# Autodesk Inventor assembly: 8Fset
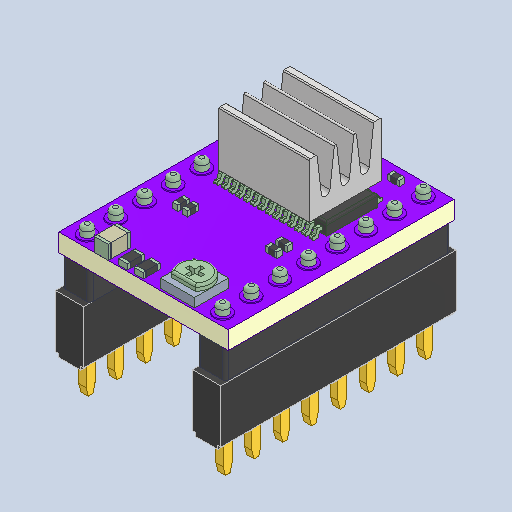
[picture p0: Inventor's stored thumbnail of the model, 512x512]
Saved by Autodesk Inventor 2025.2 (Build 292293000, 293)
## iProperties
Created: 2025-04
Part Number: 8Fset
Description: PART--DESC
Document SubType Name: Assembly
Designer: BennF
Author: BennF
Revision Number: NONE
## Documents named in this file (4)
- C:\Users\BennF\Nextcloud\Benutzer\CNC JarBeRi\existing parts\Electronics\RepRap A4988 Shied (USE WITHOUT ARDUINO)\reprap-a4988-1.snapshot.1\RepRap\RepRap\8Fset.iam
- C:\Users\BennF\Nextcloud\Benutzer\CNC JarBeRi\existing parts\Electronics\RepRap A4988 Shied (USE WITHOUT ARDUINO)\reprap-a4988-1.snapshot.1\RepRap\RepRap\8F.iam
- C:\Users\BennF\Nextcloud\Benutzer\CNC JarBeRi\existing parts\Electronics\RepRap A4988 Shied (USE WITHOUT ARDUINO)\reprap-a4988-1.snapshot.1\RepRap\RepRap\8F_1.iam
- C:\Users\BennF\Nextcloud\Benutzer\CNC JarBeRi\existing parts\Electronics\RepRap A4988 Shied (USE WITHOUT ARDUINO)\reprap-a4988-1.snapshot.1\RepRap\RepRap\DRV 8825.iam
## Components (3 placed, 2 different names)
1. 8F [sub-assembly]
2. 8F:1 [sub-assembly]
3. DRV 8825 [sub-assembly]
